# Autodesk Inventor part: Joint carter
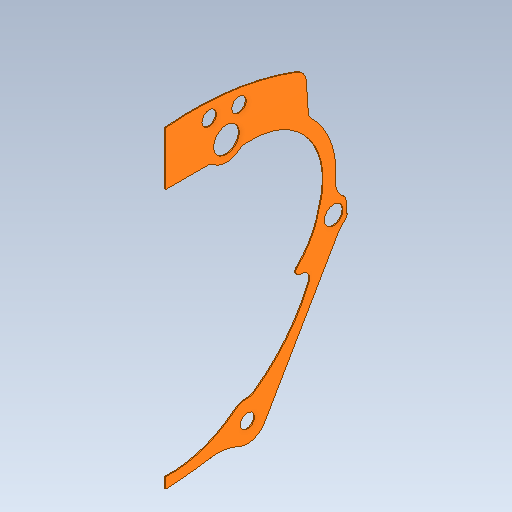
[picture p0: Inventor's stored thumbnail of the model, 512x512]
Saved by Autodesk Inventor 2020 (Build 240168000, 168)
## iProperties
Created: 2003-05
Part Number: Joint carter
Material: Générique
Document SubType Name: Modeling
Designer: Bruno
Density: 1 g/cm^3
Appearance: Par défaut
Author: Bruno
Sending System: SolidWorks 2011
Last Author: Professeur
Last Saved: 2014-11-07
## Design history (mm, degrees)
feature "coupe"
node "Solide1"
